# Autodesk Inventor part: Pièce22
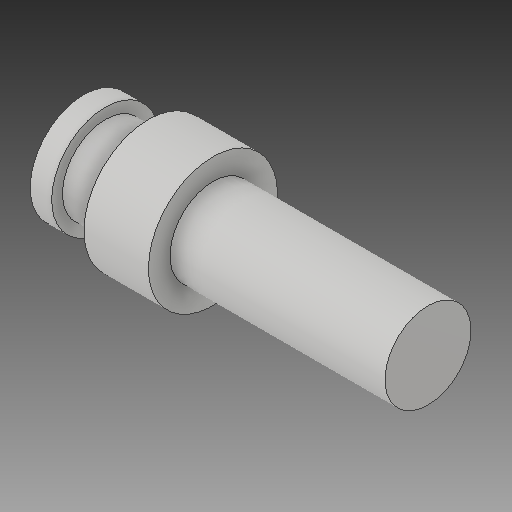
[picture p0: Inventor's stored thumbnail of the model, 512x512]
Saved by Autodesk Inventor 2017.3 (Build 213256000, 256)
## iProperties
Created: 2007-12
Part Number: Pièce22
Material: Générique
Document SubType Name: Modeling
Designer: ficho
Density: 1 g/cm^3
Appearance: Par défaut
Author: ficho
Sending System: SolidWorks 2009
Last Author: christophe
Last Saved: 2011-02-10
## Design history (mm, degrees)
feature "Révolution1"
node "Solide1"
